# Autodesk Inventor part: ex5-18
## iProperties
Created: 2006-03
Part Number: ex5-18
Document SubType Name: Modeling
Designer: Elise Moss
Author: Elise Moss
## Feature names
1. Loft1
2. Shell1
3. Extrusion1
4. Sweep1
5. FaceDraft1
6. Fillet1
7. Fillet2
